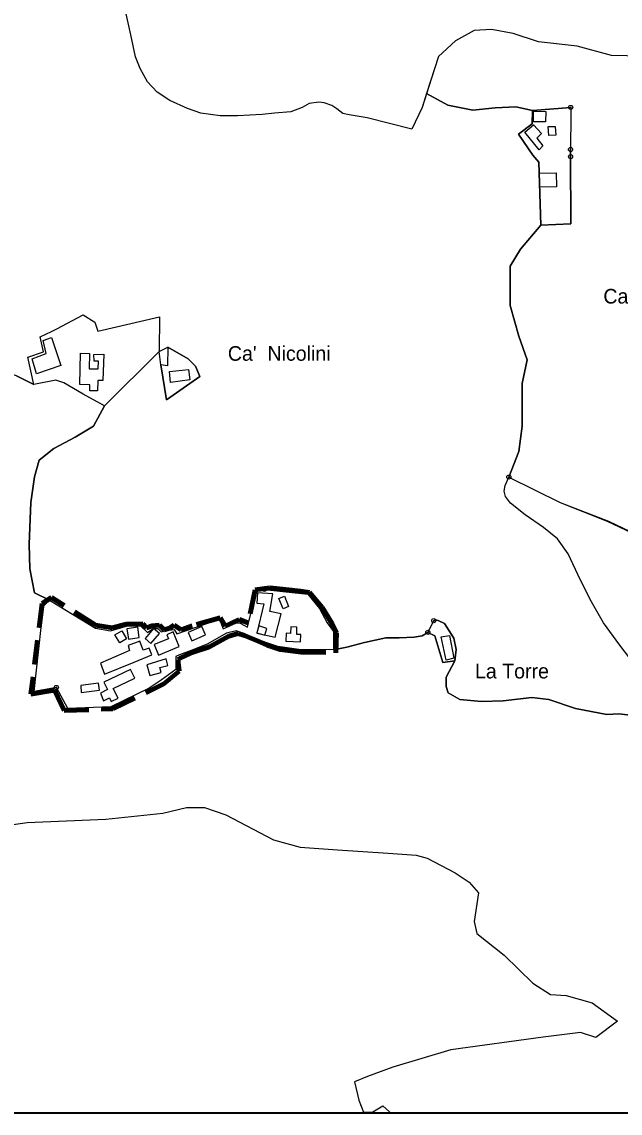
# Model space of a CAD drawing. Extents: x 652791 to 656927, y 889884 to 892405.
# Drawn here: x 655576 to 655985, y 889884 to 890630 of the extents above; entities that cross this region are included whole.
import ezdxf
from ezdxf.enums import TextEntityAlignment as Align

# ---------------------------------------------------------------- set-up
doc = ezdxf.new("R2010")
doc.units = 0
doc.header["$LTSCALE"] = 5.6
doc.header["$PDMODE"] = 32
doc.header["$PDSIZE"] = 2.8
doc.linetypes.add('MEDIUM_DASHED', pattern=[4.5, 3, -1.5])
for name, color, linetype, lineweight in [('1', 7, 'Continuous', 25), ('2', 7, 'Continuous', 25), ('36', 7, 'Continuous', 25), ('37', 7, 'Continuous', 25), ('4', 7, 'Continuous', 25), ('61', 7, 'Continuous', 35), ('7', 7, 'MEDIUM_DASHED', 100)]:
    doc.layers.add(name, color=color, linetype=linetype, lineweight=lineweight)
doc.layers.add('60', color=7, linetype='Continuous')

msp = doc.modelspace()

# ---------------------------------------------------------------- linework, layer by layer
at = {"layer": '1'}
msp.add_line((655599.3, 890175.45), (655584.18, 890172.68), dxfattribs=at)
for points in [[(655710.66, 890222.06), (655713.3, 890215.42), (655722.41, 890219.66), (655724.92, 890219.34), (655729.93, 890216.73), (655736.03, 890241.82), (655741.4, 890242.47), (655754.66, 890241.17), (655762.55, 890240.19), (655771.15, 890239.21), (655779.08, 890229.33), (655784.41, 890219.66), (655788.71, 890213.8), (655788.71, 890201.09), (655765.05, 890201.41), (655750.72, 890203.37), (655741.76, 890206.3), (655735.67, 890208.91), (655726.35, 890212.82), (655722.05, 890214.12), (655715.6, 890212.49), (655702.34, 890205), (655691.48, 890200.75), (655683.35, 890197.83), (655680.84, 890196.53), (655680.9, 890187.62), (655670.86, 890180.46), (655662.62, 890174.91), (655636.46, 890162.2), (655607.05, 890161.15), (655599.3, 890175.45)], [(655584.18, 890172.68), (655590.52, 890231.06), (655594.61, 890235.03), (655626.03, 890215.89), (655636.35, 890214.14), (655647.83, 890217.62), (655656.65, 890217.54), (655661.45, 890213.04), (655665.43, 890215.75), (655668.53, 890215.8), (655670.8, 890213.47), (655674.39, 890214.45), (655679.76, 890215.1), (655681.55, 890212.17), (655687.61, 890214.15), (655710.66, 890222.06)]]:
    msp.add_lwpolyline(points, dxfattribs=at)
for points in [[(655736.74, 890240.04), (655736.25, 890233.14), (655741.03, 890232.53), (655736.25, 890212.45), (655748.82, 890209.75), (655752.79, 890225.67), (655745.22, 890227.29), (655747.13, 890239.4)], [(655751.23, 890236.28), (655755.08, 890237.87), (655758.01, 890230.77), (655754.16, 890229.18)], [(655689.26, 890212.95), (655691.84, 890207.39), (655701.2, 890211.51), (655698.62, 890217.07)], [(655736.32, 890212.77), (655741.78, 890211.23), (655743.2, 890215.83), (655737.66, 890217.53)], [(655756.21, 890212.56), (655755.99, 890207.02), (655766.06, 890206.62), (655766.26, 890211.64), (655763.5, 890211.75), (655763.7, 890216.64), (655759.44, 890216.81), (655759.25, 890212.44)], [(655639.32, 890211.46), (655644.06, 890214.17), (655647.26, 890208.57), (655642.52, 890205.86)], [(655647.51, 890215.55), (655648.55, 890208.45), (655655.95, 890209.53), (655654.91, 890216.63)], [(655660.02, 890208.89), (655663.93, 890205.6), (655669.65, 890212.41), (655665.74, 890215.7)], [(655666.13, 890204.71), (655669.11, 890197.49), (655683.28, 890203.34), (655679.14, 890213.36), (655674.65, 890211.51), (655675.81, 890208.68)], [(655629.35, 890192.01), (655632.11, 890184.42), (655652.44, 890192.75), (655664.45, 890197.67), (655662.73, 890202.4), (655658.5, 890200.86), (655656.25, 890207.03), (655648.29, 890204.13), (655649.23, 890200.68), (655645.15, 890198.79)], [(655661.18, 890191), (655663.04, 890183.66), (655670.78, 890185.67), (655669.86, 890189.1), (655675.45, 890190.44), (655674.2, 890194.91)], [(655631.71, 890179.12), (655634.24, 890173.96), (655629.45, 890171.63), (655631.36, 890166.34), (655635.65, 890168.35), (655636.81, 890165.88), (655641.51, 890168.09), (655638.05, 890174.73), (655652.87, 890181.7), (655650, 890187.73)], [(655615.87, 890176.74), (655616.25, 890172.04), (655628.66, 890173.48), (655628.07, 890178.38)]]:
    msp.add_lwpolyline(points, close=True, dxfattribs=at)
msp.add_point((655599.3, 890175.45), dxfattribs=at)
at = {"layer": '2'}
msp.add_line((655853.15, 890213.11), (655857.95, 890210.78), dxfattribs=at)
for points in [[(655590.32, 890412.65), (655595.96, 890414.64), (655602.26, 890395.53), (655585.63, 890389.89), (655582.8, 890400.07), (655592.31, 890403.69)], [(655615.72, 890404.02), (655621.84, 890403.85), (655621.6, 890393.15), (655627.81, 890393.23), (655628.08, 890398.39), (655624.99, 890398.54), (655624.94, 890403.12), (655631.66, 890403.22), (655630.96, 890385.26), (655627.48, 890385.26), (655627.31, 890378.13), (655622.17, 890378.13), (655622.15, 890382.29), (655615.37, 890382.44)], [(655676.57, 890391.34), (655689.47, 890392.79), (655690.47, 890385.71), (655677.16, 890383.91)], [(655862.3, 890210.05), (655868.04, 890211.02), (655870.95, 890195.57), (655865.57, 890194.07)]]:
    msp.add_lwpolyline(points, close=True, dxfattribs=at)
msp.add_lwpolyline([(655857.95, 890210.78), (655863.29, 890192.4), (655871.69, 890193.57), (655872.49, 890201.37), (655870.99, 890209.17), (655864.49, 890219.17), (655860.29, 890221.17), (655858.39, 890221.77), (655857.19, 890221.07)], dxfattribs=at)
for p in [(655857.19, 890221.07), (655853.15, 890213.11)]:
    msp.add_point(p, dxfattribs=at)
at = {"layer": '36'}
for points in [[(655697.99, 890568.01), (655688.91, 890571.17), (655676.81, 890576.59), (655668.2, 890582.46), (655661.45, 890589.46), (655656.56, 890598.49), (655653.31, 890606.61), (655650.07, 890621.67), (655646.5, 890637.96), (655643.55, 890654.98), (655663.88, 890656.42), (655671.37, 890655.88), (655691.59, 890654.42)], [(655999.55, 890607.04), (655978.76, 890607.54), (655955.21, 890613.81), (655928.66, 890616.82), (655911.37, 890622.58), (655896.59, 890625.34), (655884.87, 890624.5), (655871.98, 890617.5), (655860.52, 890606.79), (655855.51, 890591.25), (655849.3, 890571.99), (655842.21, 890557.03), (655811.7, 890564.82), (655799.33, 890566.82), (655795, 890567.8), (655791.04, 890570.99), (655787.54, 890573.35), (655782.3, 890575.12), (655778.58, 890575.63), (655772.04, 890574.64), (655767.23, 890571.96), (655759.42, 890569.01), (655748.42, 890568.03), (655739.8, 890567.12), (655723.12, 890566.21), (655711.25, 890566.21), (655697.99, 890568.01)], [(656043.58, 890170.13), (656046.45, 890163.62), (656028.24, 890163.19), (656020.06, 890164.92), (656017.88, 890166.56), (656013.48, 890172.74), (655994.56, 890190.9), (655984.25, 890204.39), (655973.13, 890219.66), (655965.03, 890234.05), (655957.19, 890249.28), (655949.11, 890266.79), (655941.79, 890276.94), (655932.18, 890284.8), (655919.65, 890293.34), (655909.65, 890301.36), (655906.19, 890306.07), (655905.35, 890309.6), (655905.97, 890313.53), (655908.48, 890319.27)], [(655908.48, 890319.27), (655943.54, 890301.82), (655976.58, 890289.23), (656000.99, 890277.49)], [(655539.7, 890077.52), (655579.35, 890083.18), (655632.99, 890085.44), (655671.91, 890089.41), (655688.23, 890093.37), (655700.48, 890093.37), (655715.05, 890088.28), (655747.7, 890071.31), (655765.78, 890066.22), (655791.43, 890064.52), (655826.07, 890062.18), (655845.12, 890060.86), (655852.6, 890058.82), (655871.86, 890048.69), (655881.43, 890042.25), (655887.7, 890034.95), (655884.72, 890015.35), (655886.58, 890007.18), (655905.41, 889992.33), (655924.79, 889973.26), (655937.05, 889965.45), (655947.63, 889964.85), (655965.52, 889959.78), (655973.73, 889953.86), (655982.68, 889947.31), (655967.88, 889936.12), (655957.52, 889939.67), (655931.91, 889936.42), (655868.75, 889927.65)], [(655827.32, 889884.41), (655508.15, 889884.41), (655520.95, 889903.63), (655522.14, 889944.49)], [(655868.75, 889927.65), (655829.16, 889915.85), (655811.93, 889909.51), (655803.01, 889905.73), (655805.93, 889893.29), (655809.21, 889885.01), (655815.56, 889885.31), (655822.41, 889889.4), (655826.92, 889885.37), (655827.32, 889884.41)]]:
    msp.add_lwpolyline(points, dxfattribs=at)
at = {"layer": '37'}
msp.add_line((655908.48, 890319.27), (655943.54, 890301.82), dxfattribs=at)
for points in [[(655899.22, 890571.74), (655883.91, 890570.04), (655866.9, 890573.44), (655852.28, 890581.39), (655849.3, 890571.99), (655842.21, 890557.03), (655811.7, 890564.82), (655799.33, 890566.82), (655795, 890567.8), (655791.04, 890570.99), (655787.54, 890573.35), (655782.3, 890575.12), (655778.58, 890575.63), (655772.04, 890574.64), (655767.23, 890571.96), (655759.42, 890569.01), (655748.42, 890568.03), (655739.8, 890567.12), (655723.12, 890566.21), (655711.25, 890566.21), (655697.99, 890568.01), (655688.91, 890571.17), (655676.81, 890576.59), (655668.2, 890582.46), (655661.45, 890589.46), (655656.56, 890598.49), (655653.31, 890606.61), (655650.07, 890621.67), (655646.5, 890637.96)], [(656228.32, 890589.55), (656221.24, 890596.51), (656214.92, 890599.06), (656200.11, 890601.09), (656171.99, 890600.59), (656139.82, 890599.76), (656096.48, 890604.59), (656074.95, 890604.53), (656058.16, 890606.03), (656044.93, 890614.6), (656032.04, 890616.6), (656020.18, 890616.6), (656008.57, 890613.31), (655999.55, 890607.04), (655978.76, 890607.54), (655955.21, 890613.81), (655928.66, 890616.82), (655911.37, 890622.58), (655896.59, 890625.34), (655884.87, 890624.5), (655871.98, 890617.5), (655860.52, 890606.79), (655852.28, 890581.39)], [(655852.28, 890581.39), (655866.9, 890573.44), (655883.91, 890570.04), (655899.22, 890571.74), (655913.39, 890572.31), (655924.68, 890569.8), (655950.79, 890571.98), (655950.69, 890538.37)], [(655915.26, 890336.66), (655917.59, 890354.1), (655917.59, 890383.15), (655921.07, 890399.43), (655915.26, 890415.7), (655909.46, 890436.62), (655909.46, 890463.36), (655916.43, 890474.98), (655930.3, 890491.47), (655928.97, 890534.53), (655925.01, 890539.27), (655915.12, 890553.65), (655924.48, 890560.83), (655924.68, 890569.8), (655913.39, 890572.31), (655899.22, 890571.74)], [(655583.86, 890382.52), (655572.05, 890388.55), (655552.45, 890394.67), (655536.53, 890403.25), (655521.83, 890415.51), (655498.56, 890446.15), (655476.51, 890491.5), (655456.91, 890530.73), (655445.88, 890533.18), (655433.63, 890534.4), (655423.83, 890542.98), (655414.58, 890564.19)], [(655950.69, 890538.37), (655950.79, 890492.47), (655930.3, 890491.47)], [(655930.3, 890491.47), (655916.43, 890474.98), (655909.46, 890463.36), (655909.46, 890436.62), (655915.26, 890415.7), (655921.07, 890399.43), (655917.59, 890383.15), (655917.59, 890354.1), (655915.26, 890336.66), (655908.48, 890319.27)], [(655572.05, 890388.55), (655583.86, 890382.52), (655579.64, 890401.22), (655590.49, 890404.84), (655588.08, 890415.1), (655595.92, 890418.72), (655599.46, 890420.58), (655617.54, 890430.08), (655625.54, 890425.08), (655627.54, 890419.08), (655669.69, 890428.89), (655669.51, 890405.08), (655675.49, 890408.13), (655689.4, 890400.01), (655694.4, 890395.01), (655697.39, 890388.01), (655674.41, 890372), (655670.57, 890396.01), (655669.51, 890405.08), (655632.09, 890368.03)], [(655580.59, 890273.45), (655581.85, 890301.77), (655584.37, 890319.39), (655587.51, 890330.71), (655597.57, 890338.9), (655612.04, 890346.45), (655624.62, 890354), (655632.09, 890368.03), (655617.62, 890375.88), (655604.36, 890383.72), (655598.93, 890385.53), (655583.86, 890382.52)], [(655943.54, 890301.82), (655975.79, 890289.22), (656000.2, 890277.48), (656017.28, 890272.88), (656038.31, 890279.45), (656056.04, 890293.27), (656078.38, 890298.53), (656094.15, 890297.87), (656117.8, 890293.27), (656157.88, 890313.66), (656173.56, 890324.11), (656197.87, 890326.08), (656201.81, 890322.13), (656207.06, 890315.56), (656214.95, 890310.95), (656225.46, 890320.16), (656238.6, 890326.74), (656256.34, 890337.92), (656276.05, 890349.76), (656289.84, 890366.21), (656296.55, 890374.11), (656299.25, 890387.92)], [(655632.09, 890368.03), (655624.62, 890354), (655612.04, 890346.45), (655597.57, 890338.9), (655587.51, 890330.71), (655584.37, 890319.39), (655581.85, 890301.77), (655580.59, 890273.45)], [(655994.56, 890190.9), (655984.25, 890204.39), (655973.13, 890219.66), (655965.03, 890234.05), (655957.19, 890249.28), (655949.11, 890266.79), (655941.79, 890276.94), (655932.18, 890284.8), (655919.65, 890293.34), (655909.65, 890301.36), (655906.19, 890306.07), (655905.35, 890309.6), (655905.97, 890313.53), (655908.48, 890319.27), (655915.26, 890336.66)], [(655580.59, 890273.45), (655581.22, 890256.45), (655584.37, 890240.09), (655594.61, 890235.03), (655626.03, 890215.89), (655636.35, 890214.14), (655647.83, 890217.62), (655656.65, 890217.54), (655661.45, 890213.04), (655665.43, 890215.75), (655668.53, 890215.8), (655670.8, 890213.47), (655674.39, 890214.45), (655679.76, 890215.1), (655681.55, 890212.17), (655687.61, 890214.15), (655710.66, 890222.06)], [(655594.61, 890235.03), (655584.37, 890240.09), (655581.22, 890256.45), (655580.59, 890273.45)], [(655710.66, 890222.06), (655713.3, 890215.42), (655722.41, 890219.66), (655724.92, 890219.34), (655729.93, 890216.73), (655736.03, 890241.82), (655741.4, 890242.47)], [(655741.4, 890242.47), (655762.55, 890240.19), (655771.15, 890239.21), (655779.08, 890229.33), (655784.41, 890219.66), (655788.71, 890213.8), (655788.71, 890201.09)], [(655843.75, 890209.73), (655833.48, 890209.28), (655824.54, 890209.28), (655809.8, 890206.15), (655797.74, 890203.02), (655788.71, 890201.09), (655765.05, 890201.41), (655750.72, 890203.37), (655741.76, 890206.3), (655735.67, 890208.91), (655726.35, 890212.82), (655722.05, 890214.12), (655715.6, 890212.49), (655702.34, 890205), (655691.48, 890200.75), (655683.35, 890197.83), (655680.84, 890196.53), (655680.9, 890187.62), (655670.86, 890180.46), (655662.62, 890174.91), (655636.46, 890162.2), (655607.05, 890161.15), (655599.3, 890175.45), (655584.18, 890172.68), (655590.52, 890231.06), (655594.61, 890235.03)], [(655788.71, 890201.09), (655797.74, 890203.02), (655809.8, 890206.15), (655824.54, 890209.28), (655833.48, 890209.28), (655843.75, 890209.73), (655849.31, 890210.78), (655853.15, 890213.11), (655857.19, 890221.07), (655858.39, 890221.77), (655860.29, 890221.17), (655864.49, 890219.17), (655870.99, 890209.17), (655872.49, 890201.37), (655871.69, 890193.57)], [(656001.38, 890155.44), (655983.58, 890157.43), (655975.54, 890156.98), (655954.1, 890161), (655935.78, 890167.26), (655924.17, 890168.6), (655904.51, 890166.37), (655889.77, 890165.92), (655875.02, 890167.26), (655866.98, 890171.73), (655865.64, 890176.2), (655865.64, 890182.46), (655871.69, 890193.57), (655863.29, 890192.4), (655857.95, 890210.78), (655853.15, 890213.11), (655849.31, 890210.78), (655843.75, 890209.73)], [(655871.69, 890193.57), (655865.64, 890182.46), (655865.64, 890176.2), (655866.98, 890171.73), (655875.02, 890167.26), (655889.77, 890165.92), (655904.51, 890166.37), (655924.17, 890168.6), (655935.78, 890167.26), (655954.1, 890161), (655975.54, 890156.98), (655983.58, 890157.43), (656001.38, 890155.44)], [(655539.7, 890077.52), (655579.35, 890083.18), (655632.99, 890085.44), (655671.91, 890089.41), (655688.23, 890093.37), (655700.48, 890093.37), (655715.05, 890088.28), (655747.7, 890071.31), (655765.78, 890066.22), (655791.43, 890064.52), (655826.07, 890062.18), (655845.12, 890060.86), (655852.6, 890058.81), (655871.86, 890048.68), (655881.43, 890042.24), (655887.7, 890034.95), (655884.72, 890015.35), (655886.58, 890007.18), (655905.41, 889992.33), (655924.79, 889973.26), (655937.05, 889965.45), (655947.63, 889964.85), (655965.52, 889959.78), (655973.73, 889953.86), (655982.68, 889947.31), (655967.88, 889936.12), (655957.52, 889939.67), (655931.91, 889936.42), (655868.75, 889927.65), (655829.16, 889915.85), (655811.93, 889909.51), (655803.01, 889905.73), (655805.93, 889893.29), (655809.21, 889885.01)], [(655809.21, 889885.01), (655815.56, 889885.31), (655822.41, 889889.4), (655826.92, 889885.37), (655827.32, 889884.41), (655986.5, 889884.41)]]:
    msp.add_lwpolyline(points, dxfattribs=at)
for p in [(655950.69, 890538.37), (655908.48, 890319.27), (655741.4, 890242.47)]:
    msp.add_point(p, dxfattribs=at)
at = {"layer": '4'}
for points in [[(655950.79, 890571.98), (655924.68, 890569.8), (655924.48, 890560.83), (655915.12, 890553.65), (655925.01, 890539.27), (655928.97, 890534.53)], [(655928.97, 890534.53), (655930.3, 890491.47), (655950.79, 890492.47), (655950.69, 890538.37), (655950.68, 890543.22)]]:
    msp.add_lwpolyline(points, dxfattribs=at)
for points in [[(655925.36, 890569.4), (655933.85, 890569.2), (655933.65, 890562.03), (655925.28, 890562.23)], [(655925.28, 890560.03), (655930.86, 890554.25), (655927.67, 890551.06), (655931.8, 890545.64), (655929.2, 890543.03), (655919.5, 890555.05)], [(655935.32, 890558.97), (655940.23, 890558.84), (655940.69, 890553), (655935.78, 890552.69)], [(655929.47, 890527.13), (655940.82, 890527.33), (655941.02, 890517.76), (655929.67, 890517.56)], [(655617.62, 890375.88), (655604.36, 890383.72), (655598.93, 890385.53), (655583.86, 890382.52), (655579.64, 890401.22), (655590.49, 890404.84), (655588.08, 890415.1), (655595.92, 890418.72), (655599.46, 890420.58), (655617.54, 890430.08), (655625.54, 890425.08), (655627.54, 890419.08), (655669.69, 890428.89), (655669.51, 890405.08), (655632.09, 890368.03)], [(655670.57, 890396.01), (655674.41, 890372), (655697.39, 890388.01), (655694.4, 890395.01), (655689.4, 890400.01), (655675.49, 890408.13), (655675.17, 890395.35)]]:
    msp.add_lwpolyline(points, close=True, dxfattribs=at)
for p in [(655950.79, 890571.98), (655950.68, 890543.22)]:
    msp.add_point(p, dxfattribs=at)
at = {"layer": '61', "lineweight": 40}
msp.add_lwpolyline([(654894.04, 892404.68), (656926.84, 892404.68), (656926.84, 889884.41), (654894.04, 889884.41)], close=True, dxfattribs=at)
at = {"layer": '7'}
for points in [[(655752.19, 890201.47), (655766.52, 890199.51), (655790.18, 890199.19), (655790.74, 890212.71), (655787.73, 890218.95), (655780.85, 890230.13), (655772.26, 890240.45), (655766.11, 890241.25), (655758.22, 890242.23), (655745.18, 890243.46), (655735.08, 890242.17), (655730.35, 890219.59), (655727.12, 890220.67), (655724.12, 890221.96)], [(655724.12, 890221.96), (655714.66, 890217.23), (655711.22, 890223.03), (655692.09, 890217.66), (655684.57, 890214.86), (655679.84, 890218.09), (655676.55, 890215.9), (655672.96, 890214.92), (655669.74, 890218.09), (655664.81, 890217.58), (655660.87, 890216.28), (655658.35, 890218.95), (655647.17, 890218.73), (655637.5, 890216.15), (655625.9, 890218.09), (655596.03, 890237.02), (655589.54, 890232.82), (655581.9, 890170.76), (655597.96, 890173.58), (655604.62, 890159.6), (655637.78, 890160.84), (655663.94, 890173.55), (655672.63, 890178.01), (655683.07, 890186.48), (655682.31, 890194.63), (655684.82, 890195.93), (655692.7, 890199.51), (655703.81, 890203.1), (655717.07, 890210.59), (655723.52, 890212.22), (655727.82, 890210.92), (655737.14, 890207.01), (655743.23, 890204.4), (655752.19, 890201.47)]]:
    msp.add_lwpolyline(points, dxfattribs=at)

# ---------------------------------------------------------------- texts
at = {"layer": '60'}
for s, p in [("Ca'  di  Micheletti", (656023.81, 890437.89)), ("Ca'  Nicolini", (655751.55, 890398.78)), ('La Torre', (655910.64, 890181.61))]:
    msp.add_text(s, height=10, dxfattribs=at).set_placement(p, align=Align.CENTER)

doc.saveas('drawing.dxf')
